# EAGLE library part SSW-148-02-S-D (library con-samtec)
THROUGH-HOLE .025" SQ POST SOCKET Source: Samtec SSW.pdf
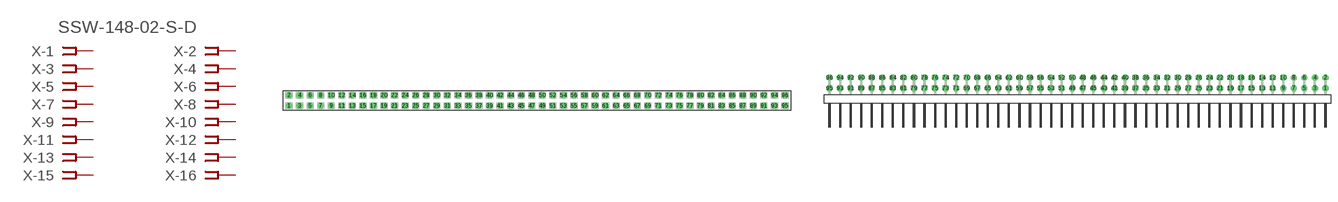
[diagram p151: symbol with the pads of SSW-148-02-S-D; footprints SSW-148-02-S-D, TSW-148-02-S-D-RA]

Designator prefix X; gates -1=FPINV -2=FPIN -3=FPIN -4=FPIN -5=FPIN -6=FPIN -7=FPIN -8=FPIN -9=FPIN -10=FPIN -11=FPIN -12=FPIN -13=FPIN -14=FPIN -15=FPIN -16=FPIN -17=FPIN -18=FPIN -19=FPIN -20=FPIN -21=FPIN -22=FPIN -23=FPIN -24=FPIN -25=FPIN -26=FPIN -27=FPIN -28=FPIN -29=FPIN -30=FPIN -31=FPIN -32=FPIN -33=FPIN -34=FPIN -35=FPIN -36=FPIN -37=FPIN -38=FPIN -39=FPIN -40=FPIN -41=FPIN -42=FPIN -43=FPIN -44=FPIN -45=FPIN -46=FPIN -47=FPIN -48=FPIN -49=FPIN -50=FPIN -51=FPIN -52=FPIN -53=FPIN -54=FPIN -55=FPIN -56=FPIN -57=FPIN -58=FPIN -59=FPIN -60=FPIN -61=FPIN -62=FPIN -63=FPIN -64=FPIN -65=FPIN -66=FPIN -67=FPIN -68=FPIN -69=FPIN -70=FPIN -71=FPIN -72=FPIN -73=FPIN -74=FPIN -75=FPIN -76=FPIN -77=FPIN -78=FPIN -79=FPIN -80=FPIN -81=FPIN -82=FPIN -83=FPIN -84=FPIN -85=FPIN -86=FPIN -87=FPIN -88=FPIN -89=FPIN -90=FPIN -91=FPIN -92=FPIN -93=FPIN -94=FPIN -95=FPIN -96=FPIN

## SSW-148-02-S-D (MPN: SSW-148-02-S-D; OC_FARNELL: unknown; OC_NEWARK: 12P0045)  [SSW-148-02-S-D]
1  -1:1  pas
2  -2:1  pas
3  -3:1  pas
4  -4:1  pas
5  -5:1  pas
6  -6:1  pas
7  -7:1  pas
8  -8:1  pas
9  -9:1  pas
10  -10:1  pas
11  -11:1  pas
12  -12:1  pas
13  -13:1  pas
14  -14:1  pas
15  -15:1  pas
16  -16:1  pas
17  -17:1  pas
18  -18:1  pas
19  -19:1  pas
20  -20:1  pas
21  -21:1  pas
22  -22:1  pas
23  -23:1  pas
24  -24:1  pas
25  -25:1  pas
26  -26:1  pas
27  -27:1  pas
28  -28:1  pas
29  -29:1  pas
30  -30:1  pas
31  -31:1  pas
32  -32:1  pas
33  -33:1  pas
34  -34:1  pas
35  -35:1  pas
36  -36:1  pas
37  -37:1  pas
38  -38:1  pas
39  -39:1  pas
40  -40:1  pas
41  -41:1  pas
42  -42:1  pas
43  -43:1  pas
44  -44:1  pas
45  -45:1  pas
46  -46:1  pas
47  -47:1  pas
48  -48:1  pas
49  -49:1  pas
50  -50:1  pas
51  -51:1  pas
52  -52:1  pas
53  -53:1  pas
54  -54:1  pas
55  -55:1  pas
56  -56:1  pas
57  -57:1  pas
58  -58:1  pas
59  -59:1  pas
60  -60:1  pas
61  -61:1  pas
62  -62:1  pas
63  -63:1  pas
64  -64:1  pas
65  -65:1  pas
66  -66:1  pas
67  -67:1  pas
68  -68:1  pas
69  -69:1  pas
70  -70:1  pas
71  -71:1  pas
72  -72:1  pas
73  -73:1  pas
74  -74:1  pas
75  -75:1  pas
76  -76:1  pas
77  -77:1  pas
78  -78:1  pas
79  -79:1  pas
80  -80:1  pas
81  -81:1  pas
82  -82:1  pas
83  -83:1  pas
84  -84:1  pas
85  -85:1  pas
86  -86:1  pas
87  -87:1  pas
88  -88:1  pas
89  -89:1  pas
90  -90:1  pas
91  -91:1  pas
92  -92:1  pas
93  -93:1  pas
94  -94:1  pas
95  -95:1  pas
96  -96:1  pas

## SSW-148-02-S-D-RA (MPN: SSW-148-02-S-D-RA; OC_FARNELL: unknown; OC_NEWARK: 12P0046)  [TSW-148-02-S-D-RA]
Pads as for SSW-148-02-S-D

## Footprint SSW-148-02-S-D (pad centres in mm)
THROUGH-HOLE .025" SQ POST SOCKET Source: Samtec SSW.pdf
drill 1 pad 1.5 octagon: 1 -59.69,-1.27; 2 -59.69,1.27; 3 -57.15,-1.27; 4 -57.15,1.27; 5 -54.61,-1.27; 6 -54.61,1.27; 7 -52.07,-1.27; 8 -52.07,1.27; 9 -49.53,-1.27; 10 -49.53,1.27; 11 -46.99,-1.27; 12 -46.99,1.27; 13 -44.45,-1.27; 14 -44.45,1.27; 15 -41.91,-1.27; 16 -41.91,1.27; 17 -39.37,-1.27; 18 -39.37,1.27; 19 -36.83,-1.27; 20 -36.83,1.27; 21 -34.29,-1.27; 22 -34.29,1.27; 23 -31.75,-1.27; 24 -31.75,1.27; 25 -29.21,-1.27; 26 -29.21,1.27; 27 -26.67,-1.27; 28 -26.67,1.27; 29 -24.13,-1.27; 30 -24.13,1.27; 31 -21.59,-1.27; 32 -21.59,1.27; 33 -19.05,-1.27; 34 -19.05,1.27; 35 -16.51,-1.27; 36 -16.51,1.27; 37 -13.97,-1.27; 38 -13.97,1.27; 39 -11.43,-1.27; 40 -11.43,1.27; 41 -8.89,-1.27; 42 -8.89,1.27; 43 -6.35,-1.27; 44 -6.35,1.27; 45 -3.81,-1.27; 46 -3.81,1.27; 47 -1.27,-1.27; 48 -1.27,1.27; 49 1.27,-1.27; 50 1.27,1.27; 51 3.81,-1.27; 52 3.81,1.27; 53 6.35,-1.27; 54 6.35,1.27; 55 8.89,-1.27; 56 8.89,1.27; 57 11.43,-1.27; 58 11.43,1.27; 59 13.97,-1.27; 60 13.97,1.27; 61 16.51,-1.27; 62 16.51,1.27; 63 19.05,-1.27; 64 19.05,1.27; 65 21.59,-1.27; 66 21.59,1.27; 67 24.13,-1.27; 68 24.13,1.27; 69 26.67,-1.27; 70 26.67,1.27; 71 29.21,-1.27; 72 29.21,1.27; 73 31.75,-1.27; 74 31.75,1.27; 75 34.29,-1.27; 76 34.29,1.27; 77 36.83,-1.27; 78 36.83,1.27; 79 39.37,-1.27; 80 39.37,1.27; 81 41.91,-1.27; 82 41.91,1.27; 83 44.45,-1.27; 84 44.45,1.27; 85 46.99,-1.27; 86 46.99,1.27; 87 49.53,-1.27; 88 49.53,1.27; 89 52.07,-1.27; 90 52.07,1.27; 91 54.61,-1.27; 92 54.61,1.27; 93 57.15,-1.27; 94 57.15,1.27; 95 59.69,-1.27; 96 59.69,1.27

## Footprint TSW-148-02-S-D-RA (pad centres in mm)
THROUGH-HOLE .025" SQ POST HEADER Source: Samtec TSW.pdf
drill 1 pad 1.5 octagon: 1 59.69,1.524; 2 59.69,4.064; 3 57.15,1.524; 4 57.15,4.064; 5 54.61,1.524; 6 54.61,4.064; 7 52.07,1.524; 8 52.07,4.064; 9 49.53,1.524; 10 49.53,4.064; 11 46.99,1.524; 12 46.99,4.064; 13 44.45,1.524; 14 44.45,4.064; 15 41.91,1.524; 16 41.91,4.064; 17 39.37,1.524; 18 39.37,4.064; 19 36.83,1.524; 20 36.83,4.064; 21 34.29,1.524; 22 34.29,4.064; 23 31.75,1.524; 24 31.75,4.064; 25 29.21,1.524; 26 29.21,4.064; 27 26.67,1.524; 28 26.67,4.064; 29 24.13,1.524; 30 24.13,4.064; 31 21.59,1.524; 32 21.59,4.064; 33 19.05,1.524; 34 19.05,4.064; 35 16.51,1.524; 36 16.51,4.064; 37 13.97,1.524; 38 13.97,4.064; 39 11.43,1.524; 40 11.43,4.064; 41 8.89,1.524; 42 8.89,4.064; 43 6.35,1.524; 44 6.35,4.064; 45 3.81,1.524; 46 3.81,4.064; 47 1.27,1.524; 48 1.27,4.064; 49 -1.27,1.524; 50 -1.27,4.064; 51 -3.81,1.524; 52 -3.81,4.064; 53 -6.35,1.524; 54 -6.35,4.064; 55 -8.89,1.524; 56 -8.89,4.064; 57 -11.43,1.524; 58 -11.43,4.064; 59 -13.97,1.524; 60 -13.97,4.064; 61 -16.51,1.524; 62 -16.51,4.064; 63 -19.05,1.524; 64 -19.05,4.064; 65 -21.59,1.524; 66 -21.59,4.064; 67 -24.13,1.524; 68 -24.13,4.064; 69 -26.67,1.524; 70 -26.67,4.064; 71 -29.21,1.524; 72 -29.21,4.064; 73 -31.75,1.524; 74 -31.75,4.064; 75 -34.29,1.524; 76 -34.29,4.064; 77 -36.83,1.524; 78 -36.83,4.064; 79 -39.37,1.524; 80 -39.37,4.064; 81 -41.91,1.524; 82 -41.91,4.064; 83 -44.45,1.524; 84 -44.45,4.064; 85 -46.99,1.524; 86 -46.99,4.064; 87 -49.53,1.524; 88 -49.53,4.064; 89 -52.07,1.524; 90 -52.07,4.064; 91 -54.61,1.524; 92 -54.61,4.064; 93 -57.15,1.524; 94 -57.15,4.064; 95 -59.69,1.524; 96 -59.69,4.064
